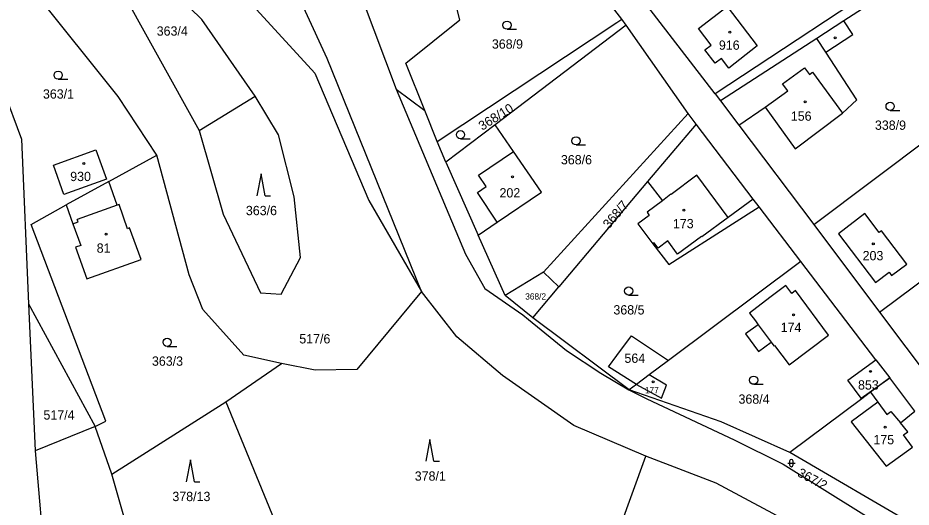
# Model space of a CAD drawing. Extents: x -725728 to -720881, y -1068679 to -1063504.
# Drawn here: x -723846.7 to -723683.2, y -1066913.6 to -1066824.1 of the extents above; entities that cross this region are included whole.
import ezdxf

# ---------------------------------------------------------------- set-up
doc = ezdxf.new("R2010")
doc.units = 0
for name, color, linetype in [('Hranice parcel', 7, 'Continuous'), ('Parcelní čísla', 7, 'Continuous'), ('Vnitřní kresba', 7, 'Continuous'), ('Značky budov', 7, 'Continuous'), ('Značky kultur', 7, 'Continuous')]:
    doc.layers.add(name, color=color, linetype=linetype)

# ---------------------------------------------------------------- blocks, each defined once
blk = doc.blocks.new('4.02_4')
at = {"layer": 'Značky budov'}
blk.add_circle((-0.001, 0), 0.0175, dxfattribs=at)
blk = doc.blocks.new('4.02_3')
at = {"layer": 'Značky budov'}
blk.add_circle((-0.001, 0), 0.0175, dxfattribs=at)
blk = doc.blocks.new('3.04_2')
at = {"layer": 'Značky kultur'}
blk.add_line((0.001, 0), (0.176, 0), dxfattribs=at)
blk.add_circle((0.001, 0.075), 0.075, dxfattribs=at)
blk = doc.blocks.new('3.04_3')
at = {"layer": 'Značky kultur'}
blk.add_line((0.001, 0), (0.176, 0), dxfattribs=at)
blk.add_circle((0.001, 0.075), 0.075, dxfattribs=at)
blk = doc.blocks.new('3.08_1')
at = {"layer": 'Značky kultur'}
for p, q in [((0, 0.4), (-0.075, 0)), ((0.075, 0), (0, 0.4)), ((0.075, 0), (0.175, 0))]:
    blk.add_line(p, q, dxfattribs=at)
blk = doc.blocks.new('3.08_2')
at = {"layer": 'Značky kultur'}
for p, q in [((0, 0.4), (-0.075, 0)), ((0.075, 0), (0, 0.4)), ((0.075, 0), (0.175, 0))]:
    blk.add_line(p, q, dxfattribs=at)
blk = doc.blocks.new('3.16_4')
at = {"layer": 'Značky kultur'}
for p, q in [((-0.067, 0.067), (0.067, 0.067)), ((-0.034, 0.101), (-0.034, 0.033)), ((0.033, 0.033), (0.033, 0.101))]:
    blk.add_line(p, q, dxfattribs=at)
for centre, start, end in [((0, 0.1), 0, 180), ((0, 0.033), 180, 359.9879)]:
    blk.add_arc(centre, 0.0335, start, end, dxfattribs=at)

msp = doc.modelspace()

# ---------------------------------------------------------------- linework, layer by layer
at = {"layer": 'Hranice parcel'}
for p, q in [((-723719.06, -1066837.93), (-723731.41, -1066822)), ((-723735.34, -1066825.42), (-723759.32, -1066843.6)), ((-723735.34, -1066825.42), (-723736.18, -1066824.32)), ((-723724.03, -1066841.57), (-723735.34, -1066825.42)), ((-723777.46, -1066837.1), (-723772.18, -1066840.99)), ((-723701.03, -1066861.86), (-723666.7, -1066836.05)), ((-723813.49, -1066844.67), (-723803.27, -1066838.36)), ((-723719.06, -1066837.93), (-723718.1, -1066839.23)), ((-723718.1, -1066839.23), (-723714.76, -1066843.66)), ((-723769.91, -1066846.65), (-723772.18, -1066840.99)), ((-723750.47, -1066870.57), (-723724.03, -1066841.57)), ((-723722.54, -1066843.48), (-723724.03, -1066841.57)), ((-723759.32, -1066843.6), (-723768.38, -1066850.46)), ((-723722.54, -1066843.48), (-723731.43, -1066854.02)), ((-723714.76, -1066843.66), (-723701.03, -1066861.86)), ((-723768.38, -1066850.46), (-723769.91, -1066846.65)), ((-723830.02, -1066854.02), (-723821.23, -1066849.15)), ((-723768.38, -1066850.46), (-723762.43, -1066863.79)), ((-723830.02, -1066854.02), (-723837.8, -1066858.25)), ((-723731.43, -1066854.02), (-723747.68, -1066873.29)), ((-723703.42, -1066868.62), (-723711.03, -1066858.64)), ((-723688.98, -1066877.88), (-723664.27, -1066859.36)), ((-723701.03, -1066861.86), (-723688.98, -1066877.88)), ((-723757.48, -1066874.87), (-723762.43, -1066863.79)), ((-723703.42, -1066868.62), (-723727.64, -1066886.74)), ((-723689.66, -1066886.62), (-723703.42, -1066868.62)), ((-723750.47, -1066870.57), (-723757.48, -1066874.87)), ((-723747.68, -1066873.29), (-723750.47, -1066870.57)), ((-723752.44, -1066878.94), (-723747.68, -1066873.29)), ((-723752.44, -1066878.94), (-723757.48, -1066874.87)), ((-723844.74, -1066876.41), (-723843.47, -1066903.29)), ((-723844.74, -1066876.41), (-723832.52, -1066898.8)), ((-723734.8, -1066892.1), (-723752.44, -1066878.94)), ((-723713.55, -1066881.86), (-723711.17, -1066885.08)), ((-723808.62, -1066894.3), (-723798.43, -1066887.3)), ((-723727.64, -1066886.74), (-723731.13, -1066889.35)), ((-723689.66, -1066886.62), (-723687.11, -1066889.94)), ((-723731.13, -1066889.35), (-723733.49, -1066891.12)), ((-723733.49, -1066891.12), (-723734.8, -1066892.1)), ((-723687.11, -1066889.94), (-723690.62, -1066892.56)), ((-723682.53, -1066896.01), (-723687.11, -1066889.94)), ((-723690.62, -1066892.56), (-723692.23, -1066893.76)), ((-723829.45, -1066907.57), (-723808.62, -1066894.3)), ((-723808.62, -1066894.3), (-723799.78, -1066915.85)), ((-723692.23, -1066893.76), (-723705.39, -1066903.57)), ((-723832.52, -1066898.8), (-723843.47, -1066903.29)), ((-723829.45, -1066907.57), (-723832.52, -1066898.8)), ((-723741.76, -1066931.62), (-723731.76, -1066904.24)), ((-723670.85, -1066923.75), (-723705.39, -1066903.57)), ((-723825.61, -1066921.06), (-723829.45, -1066907.57))]:
    msp.add_line(p, q, dxfattribs=at)
for points in [[(-723736.18, -1066824.32), (-723737.88, -1066822.12), (-723747.44, -1066809.73), (-723767.08, -1066785.15)], [(-723822.39, -1066801.28), (-723792.35, -1066834.18), (-723782.47, -1066857.47), (-723772.78, -1066874.14), (-723790.04, -1066831.48), (-723801.95, -1066805.61), (-723811.56, -1066790.04), (-723817.79, -1066789.91), (-723822.66, -1066794.51), (-723822.39, -1066801.28)], [(-723796.13, -1066791.39), (-723789.5, -1066804.93), (-723777.46, -1066837.1)], [(-723772.18, -1066840.99), (-723775.66, -1066832.33), (-723765.79, -1066824.42), (-723774.26, -1066790.88)], [(-723803.27, -1066838.36), (-723812.99, -1066824.35), (-723828.38, -1066809.32), (-723832.04, -1066804.65), (-723833.43, -1066800.86), (-723833.53, -1066797.67)], [(-723692.44, -1066798.16), (-723683.88, -1066814.7), (-723719.06, -1066837.93)], [(-723838.61, -1066804.15), (-723828.89, -1066816.9), (-723813.49, -1066844.67)], [(-723821.23, -1066849.15), (-723828.32, -1066838.46), (-723843.47, -1066819.39), (-723849.08, -1066815.73), (-723853.94, -1066822.36), (-723852.74, -1066828.17), (-723845.99, -1066846.28), (-723844.74, -1066876.41)], [(-723666.7, -1066836.05), (-723682.74, -1066816.33), (-723695.5, -1066824.59)], [(-723716.6, -1066833.23), (-723717.91, -1066831.49), (-723719.08, -1066832.35), (-723720.95, -1066829.91), (-723719.79, -1066829.04), (-723722.1, -1066826.01), (-723716.88, -1066821.99), (-723711.37, -1066829.2), (-723716.6, -1066833.23)], [(-723769.91, -1066846.65), (-723737.04, -1066824.89), (-723736.18, -1066824.32)], [(-723695.5, -1066824.59), (-723700.46, -1066827.81), (-723718.1, -1066839.23)], [(-723714.76, -1066843.66), (-723709.92, -1066840.4), (-723704.42, -1066847.99), (-723695.8, -1066841.49), (-723693.17, -1066839.07), (-723698.84, -1066830.31), (-723693.88, -1066827.1), (-723695.5, -1066824.59)], [(-723777.46, -1066837.1), (-723764.73, -1066867.3), (-723761.23, -1066873.57), (-723754.27, -1066878.39), (-723753.2, -1066879.22), (-723746.25, -1066884.93), (-723739.98, -1066889.04), (-723734.84, -1066892.14), (-723731.55, -1066893.76), (-723715.57, -1066901.25), (-723706.63, -1066905.7), (-723684.27, -1066919.67), (-723678.75, -1066923.12), (-723670.82, -1066928.35), (-723648.47, -1066945.13), (-723643.77, -1066949.29), (-723621.72, -1066990.67)], [(-723813.49, -1066844.67), (-723809.08, -1066859.95), (-723802.26, -1066874.34), (-723798.48, -1066874.6), (-723794.94, -1066867.9), (-723796.08, -1066856.79), (-723798.98, -1066845.43), (-723803.27, -1066838.36)], [(-723762.43, -1066863.79), (-723758.94, -1066861.42), (-723750.86, -1066855.92), (-723755.95, -1066848.51), (-723759.32, -1066843.6)], [(-723711.03, -1066858.64), (-723712.09, -1066857.24), (-723722.54, -1066843.48)], [(-723838.23, -1066856.38), (-723840.14, -1066851.01), (-723832.37, -1066848.22), (-723830.47, -1066853.6), (-723838.23, -1066856.38)], [(-723798.43, -1066887.3), (-723805.34, -1066885.77), (-723812.79, -1066877.43), (-723815.31, -1066871.07), (-723821.23, -1066849.15)], [(-723837.8, -1066858.25), (-723836.58, -1066861.73), (-723835.16, -1066865.7), (-723836.1, -1066866.04), (-723834.04, -1066871.8), (-723824.12, -1066868.25), (-723826.21, -1066862.49), (-723826.62, -1066862.63), (-723828.12, -1066858.2), (-723828.49, -1066858.33), (-723830.02, -1066854.02)], [(-723731.43, -1066854.02), (-723728.72, -1066857.56), (-723731.53, -1066859.62), (-723731.12, -1066860.19), (-723733.25, -1066861.75), (-723730.46, -1066865.39), (-723727.55, -1066869.18), (-723715.89, -1066861.74), (-723711.03, -1066858.64)], [(-723832.52, -1066898.8), (-723830.54, -1066897.84), (-723844.24, -1066861.88), (-723837.8, -1066858.25)], [(-723696.53, -1066863.58), (-723689.75, -1066872.49), (-723687.26, -1066870.58), (-723686.78, -1066871.22), (-723684.01, -1066869.1), (-723688.66, -1066863.02), (-723689.06, -1066863.32), (-723691.68, -1066859.88), (-723696.53, -1066863.58)], [(-723711.17, -1066885.08), (-723708.82, -1066883.42), (-723708.33, -1066884.09), (-723708.2, -1066883.99), (-723705.51, -1066887.56), (-723698.31, -1066882.11), (-723704.35, -1066873.96), (-723705.07, -1066874.5), (-723706.15, -1066873.04), (-723709.09, -1066875.25), (-723712.81, -1066878.06), (-723711.71, -1066879.52), (-723711.2, -1066880.21), (-723713.55, -1066881.86)], [(-723731.76, -1066904.24), (-723744.93, -1066898.67), (-723757.98, -1066889.51), (-723766.32, -1066882.43), (-723772.78, -1066874.14), (-723784.62, -1066888.4), (-723792.29, -1066888.51), (-723798.43, -1066887.3)], [(-723688.98, -1066877.88), (-723679.38, -1066890.69), (-723677.06, -1066893.89)], [(-723733.49, -1066891.12), (-723738.6, -1066887.91), (-723737.06, -1066885.84), (-723734.39, -1066882.26), (-723727.64, -1066886.74)], [(-723692.23, -1066893.76), (-723692.33, -1066893.63), (-723694.81, -1066890.33), (-723689.66, -1066886.62)], [(-723733.49, -1066891.12), (-723728.91, -1066893.67), (-723727.95, -1066891.24), (-723731.13, -1066889.35)], [(-723705.39, -1066903.57), (-723717.98, -1066898), (-723734.8, -1066892.1)], [(-723690.62, -1066892.56), (-723689.29, -1066894.37), (-723694.16, -1066897.95), (-723687.76, -1066906.07), (-723682.96, -1066902.61), (-723684.58, -1066900.37), (-723683.82, -1066899.82), (-723685.17, -1066898.18), (-723682.53, -1066896.01)], [(-723843.47, -1066903.29), (-723841.59, -1066925.23), (-723837.09, -1066931.36)], [(-723702.29, -1066918.22), (-723708.5, -1066914.76), (-723718.9, -1066909.21), (-723731.76, -1066904.24)]]:
    msp.add_lwpolyline(points, dxfattribs=at)
at = {"layer": 'Vnitřní kresba'}
for p, q in [((-723698.84, -1066830.31), (-723700.46, -1066827.81)), ((-723706.75, -1066836.1), (-723702.71, -1066833.17)), ((-723702.71, -1066833.17), (-723701.82, -1066834.41)), ((-723701.82, -1066834.41), (-723701.24, -1066833.99)), ((-723701.24, -1066833.99), (-723695.8, -1066841.49)), ((-723705.8, -1066837.42), (-723706.75, -1066836.1)), ((-723709.92, -1066840.4), (-723705.8, -1066837.42)), ((-723762.39, -1066852.82), (-723755.95, -1066848.51)), ((-723760.99, -1066854.92), (-723762.39, -1066852.82)), ((-723722.43, -1066852.82), (-723727.11, -1066856.38)), ((-723716.71, -1066860.61), (-723722.43, -1066852.82)), ((-723762.58, -1066855.98), (-723760.99, -1066854.92)), ((-723758.94, -1066861.42), (-723762.58, -1066855.98)), ((-723727.17, -1066856.3), (-723728.72, -1066857.56)), ((-723727.11, -1066856.38), (-723727.17, -1066856.3)), ((-723828.49, -1066858.33), (-723835.8, -1066860.92)), ((-723712.09, -1066857.24), (-723716.71, -1066860.61)), ((-723836.58, -1066861.73), (-723835.63, -1066861.39)), ((-723835.63, -1066861.39), (-723835.8, -1066860.92)), ((-723716.71, -1066860.61), (-723721.49, -1066864.12)), ((-723727.74, -1066864.88), (-723729.51, -1066866.17)), ((-723725.97, -1066867.29), (-723727.74, -1066864.88)), ((-723721.55, -1066864.04), (-723725.97, -1066867.29)), ((-723721.49, -1066864.12), (-723721.55, -1066864.04)), ((-723730.21, -1066865.21), (-723730.46, -1066865.39)), ((-723729.51, -1066866.17), (-723730.21, -1066865.21)), ((-723711.2, -1066880.21), (-723708.82, -1066883.42)), ((-723692.33, -1066893.63), (-723687.11, -1066889.94)), ((-723689.29, -1066894.37), (-723687.64, -1066896.62)), ((-723687.64, -1066896.62), (-723686.9, -1066896.08)), ((-723686.9, -1066896.08), (-723685.17, -1066898.18))]:
    msp.add_line(p, q, dxfattribs=at)

# ---------------------------------------------------------------- block references
at = {"layer": 'Značky budov', "xscale": 10, "yscale": 10}
for name, p in [('4.02_4', (-723716.36, -1066826.66)), ('4.02_3', (-723697.11, -1066827.69)), ('4.02_4', (-723702.58, -1066839.4)), ('4.02_3', (-723834.6, -1066850.69)), ('4.02_4', (-723756.14, -1066853.14)), ('4.02_3', (-723724.77, -1066859.26)), ('4.02_4', (-723830.52, -1066863.63)), ('4.02_4', (-723690.12, -1066865.4)), ('4.02_4', (-723704.7, -1066878.41)), ('4.02_3', (-723690.65, -1066888.74)), ('4.02_4', (-723730.39, -1066890.65)), ('4.02_3', (-723687.96, -1066898.95))]:
    msp.add_blockref(name, p, dxfattribs=at)
at = {"layer": 'Značky kultur', "xscale": 10, "yscale": 10}
for name, p in [('3.04_3', (-723757.16, -1066826.14)), ('3.04_2', (-723839.31, -1066835.28)), ('3.04_2', (-723687.07, -1066840.99)), ('3.04_2', (-723765.69, -1066846.19)), ('3.04_2', (-723744.53, -1066847.31)), ('3.08_1', (-723802.17, -1066856.61)), ('3.04_2', (-723734.92, -1066874.78)), ('3.04_3', (-723819.36, -1066884.16)), ('3.04_2', (-723712.03, -1066891.11)), ('3.08_1', (-723771.27, -1066905.19)), ('3.08_2', (-723815.09, -1066908.93)), ('3.16_4', (-723705.13, -1066906.19))]:
    msp.add_blockref(name, p, dxfattribs=at)

# ---------------------------------------------------------------- texts
at = {"layer": 'Parcelní čísla'}
for s, height, p in [('363/4', 1.7, (-723821.26, -1066827.31)), ('368/9', 1.7, (-723759.93, -1066829.69)), ('916', 1.7, (-723718.39, -1066829.89)), ('363/1', 1.7, (-723842.08, -1066838.83)), ('156', 1.7, (-723705.23, -1066842.88)), ('338/9', 1.7, (-723689.84, -1066844.54)), ('368/6', 1.7, (-723747.3, -1066850.86)), ('930', 1.7, (-723837.09, -1066853.92)), ('202', 1.7, (-723758.53, -1066856.92)), ('363/6', 1.7, (-723804.94, -1066860.16)), ('173', 1.7, (-723726.8, -1066862.55)), ('81', 1.7, (-723832.24, -1066867.03)), ('203', 1.7, (-723692.09, -1066868.41)), ('368/2', 1.14, (-723753.83, -1066875.6)), ('368/5', 1.7, (-723737.69, -1066878.33)), ('174', 1.7, (-723707.08, -1066881.53)), ('517/6', 1.7, (-723795.17, -1066883.63)), ('363/3', 1.7, (-723822.13, -1066887.71)), ('564', 1.7, (-723735.67, -1066887.18)), ('853', 1.7, (-723692.93, -1066892.07)), ('177', 1.14, (-723731.92, -1066892.74)), ('368/4', 1.7, (-723714.8, -1066894.66)), ('517/4', 1.7, (-723841.98, -1066897.57)), ('175', 1.7, (-723690.12, -1066902.09)), ('378/1', 1.7, (-723774.04, -1066908.74)), ('378/13', 1.7, (-723818.39, -1066912.48))]:
    msp.add_text(s, height=height, dxfattribs=at).set_placement(p)
for s, rotation, p in [('368/10', 32, (-723761.7, -1066844.73)), ('368/7', 50, (-723738.49, -1066862.74)), ('367/2', 332, (-723704.16, -1066907.84))]:
    msp.add_text(s, height=1.7, rotation=rotation, dxfattribs=at).set_placement(p)

doc.saveas('drawing.dxf')
